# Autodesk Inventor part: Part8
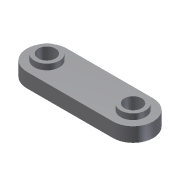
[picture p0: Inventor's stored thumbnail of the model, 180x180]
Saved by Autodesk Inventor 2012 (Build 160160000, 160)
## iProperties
Shininess: 77.0
Length Units: 11269
Angle Units: 11279
Time Units: 11290
Mass Units: 11283
Length Display Precision: 3
Angle Display Precision: 2
Created: 2002-01
Part Number: Part8
Document SubType Name: Modeling
Designer: ***
Density: 1 g/cm^3
Material: Default
Density: 0.0
Volumn: 0.0
Area: 0.0
PropertySet Name: Model Information
Control State: 0
Master: False
Checked Out: False
Author: ***
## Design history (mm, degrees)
sketch "Sketch1"
  geometry: L1 (-33.118, 12.346)-(26.882, 12.361); L2 (-33.111, -15.654)-(26.889, -15.639); C1 r 6 at (-33.114, -1.654); C2 r 6 at (26.886, -1.639); A1 r 14 centre (-33.114, -1.654) between (-33.118, 12.346) and (-33.111, -15.654); A2 r 14 centre (26.886, -1.639) between (26.889, -15.639) and (26.882, 12.361)
  constraints: 4 centre point, 4 end point, 4 point on circle, 4 tangent, 2 coincident, 2 equal radius
  dimensions: "d0" = 60 distance of L1.start L1.end; "d1" = 14 radius of A1; "d2" = 12 diameter of C1
extrude "Extrusion1" new body sketch "Sketch1" distance "d3" = 10; taper "d4" = 0 deg
sketch "Sketch2"
  geometry: C1 r 6 at (26.886, -1.639) reference; C2 r 6 at (-33.114, -1.654) reference; C3 r 8.694 at (-33.114, -1.654); C4 r 8.694 at (26.886, -1.639)
  constraints: 2 centre point, 2 coincident, 1 equal radius
extrude "Extrusion2" join sketch "Sketch2" distance "d5" = 4; taper "d6" = 0 deg
body "Solid1"
